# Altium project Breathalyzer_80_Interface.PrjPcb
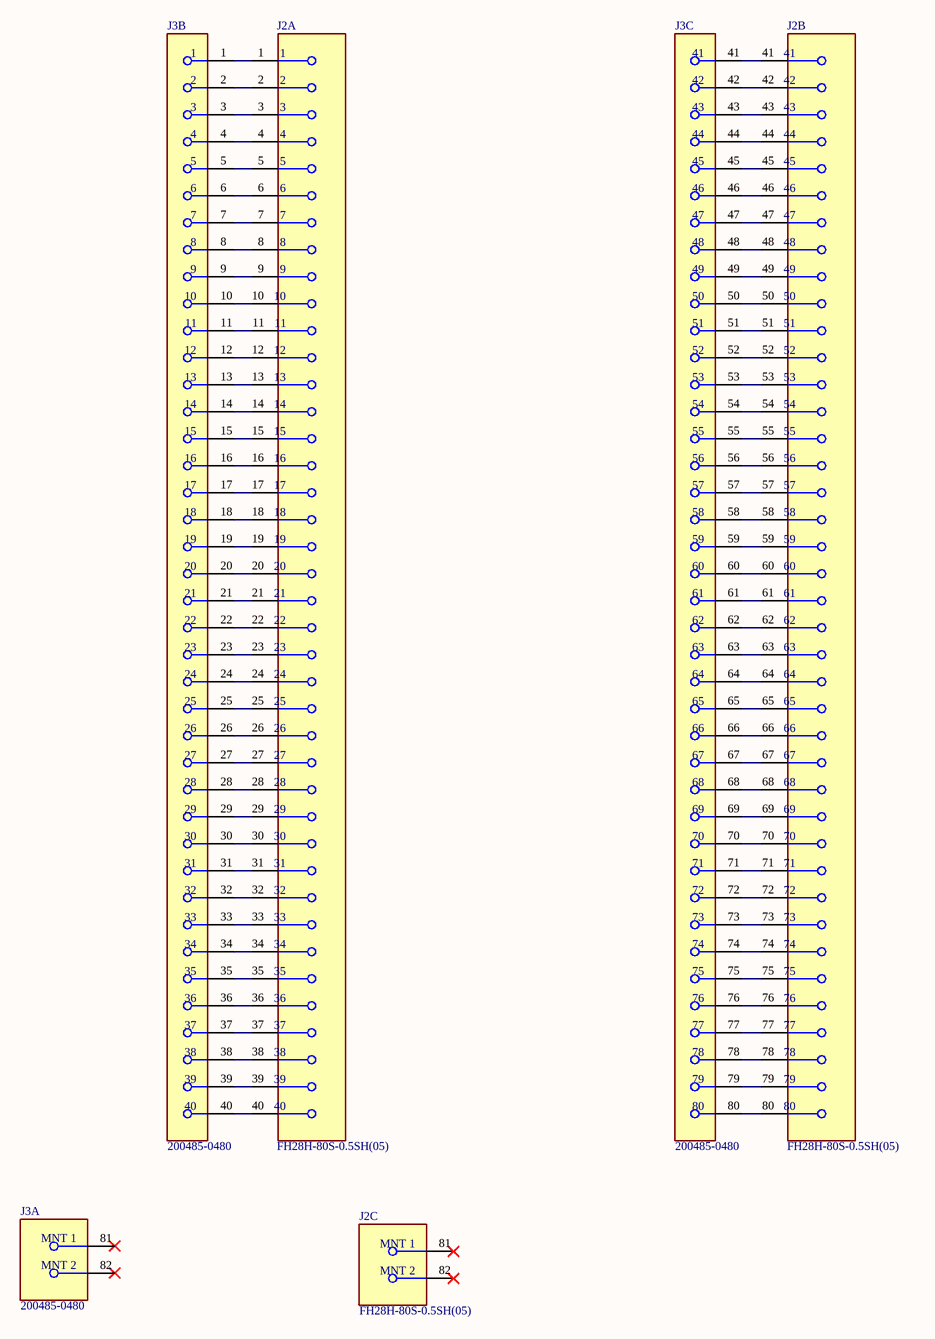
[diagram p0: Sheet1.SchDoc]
CAGE_CODE: ?????; CONTRACT_NUMBER: <CONTRACT NO>; DOC_NO_ASSY_DWG: <ASSY DWG NO>; DOC_NO_BOM: <BOM DOC NO>; DOC_NO_FAB_DWG: <FAB DWG NO>; DOC_NO_SCH_DWG: <SCH DWG NO>; PCB_2_DEC_TOL: +/-.01; PCB_3_DEC_TOL: +/-.010; PCB_ANG_TOL: +/-1/2; PCB_ASSEMBLY_NO: <PCB ASSY NO>; PCB_CHECKER: - -----; PCB_CHECKER_APP_DATE: --/--/----; PCB_DESIGNER: - -----; PCB_DESIGNER_APP_DATE: --/--/----; PCB_DWG_NO: <PCB DWG NO>; PCB_ENGINEER: - -----; PCB_ENGINEER_APP_DATE: --/--/----; PCB_PART_NUMBER: <PCB PN>; PCB_REV: A; SCH_REV: A
1 sheet, 2 parts. Net scope: global (net labels, ports and power ports of the same name join across sheets).
Board file: PCB1.PcbDoc

## Sheet Sheet1.SchDoc
size 431 x 279 mm; SheetNumber: 1; SheetTotal: 1; ENG_APP_DATE: --/--/--; DSN_APP_DATE: --/--/--; CHK_APP_DATE: --/--/--

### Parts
J2  FH28H-80S-0.5SH(05)  [FP-FH28H-80S-0_5SH_05-MFG]  (parts A,B,C of 3)
J3  200485-0480  [FP-200485-0480-MFG]  (parts A,B,C of 3)

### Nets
NetJ2_1: J2.1 J3.1
NetJ2_2: J2.2 J3.2
NetJ2_3: J2.3 J3.3
NetJ2_4: J2.4 J3.4
NetJ2_5: J2.5 J3.5
NetJ2_6: J2.6 J3.6
NetJ2_7: J2.7 J3.7
NetJ2_8: J2.8 J3.8
NetJ2_9: J2.9 J3.9
NetJ2_10: J2.10 J3.10
NetJ2_11: J2.11 J3.11
NetJ2_12: J2.12 J3.12
NetJ2_13: J2.13 J3.13
NetJ2_14: J2.14 J3.14
NetJ2_15: J2.15 J3.15
NetJ2_16: J2.16 J3.16
NetJ2_17: J2.17 J3.17
NetJ2_18: J2.18 J3.18
NetJ2_19: J2.19 J3.19
NetJ2_20: J2.20 J3.20
NetJ2_21: J2.21 J3.21
NetJ2_22: J2.22 J3.22
NetJ2_23: J2.23 J3.23
NetJ2_24: J2.24 J3.24
NetJ2_25: J2.25 J3.25
NetJ2_26: J2.26 J3.26
NetJ2_27: J2.27 J3.27
NetJ2_28: J2.28 J3.28
NetJ2_29: J2.29 J3.29
NetJ2_30: J2.30 J3.30
NetJ2_31: J2.31 J3.31
NetJ2_32: J2.32 J3.32
NetJ2_33: J2.33 J3.33
NetJ2_34: J2.34 J3.34
NetJ2_35: J2.35 J3.35
NetJ2_36: J2.36 J3.36
NetJ2_37: J2.37 J3.37
NetJ2_38: J2.38 J3.38
NetJ2_39: J2.39 J3.39
NetJ2_40: J2.40 J3.40
NetJ2_41: J2.41 J3.41
NetJ2_42: J2.42 J3.42
NetJ2_43: J2.43 J3.43
NetJ2_44: J2.44 J3.44
NetJ2_45: J2.45 J3.45
NetJ2_46: J2.46 J3.46
NetJ2_47: J2.47 J3.47
NetJ2_48: J2.48 J3.48
NetJ2_49: J2.49 J3.49
NetJ2_50: J2.50 J3.50
NetJ2_51: J2.51 J3.51
NetJ2_52: J2.52 J3.52
NetJ2_53: J2.53 J3.53
NetJ2_54: J2.54 J3.54
NetJ2_55: J2.55 J3.55
NetJ2_56: J2.56 J3.56
NetJ2_57: J2.57 J3.57
NetJ2_58: J2.58 J3.58
NetJ2_59: J2.59 J3.59
NetJ2_60: J2.60 J3.60
NetJ2_61: J2.61 J3.61
NetJ2_62: J2.62 J3.62
NetJ2_63: J2.63 J3.63
NetJ2_64: J2.64 J3.64
NetJ2_65: J2.65 J3.65
NetJ2_66: J2.66 J3.66
NetJ2_67: J2.67 J3.67
NetJ2_68: J2.68 J3.68
NetJ2_69: J2.69 J3.69
NetJ2_70: J2.70 J3.70
NetJ2_71: J2.71 J3.71
NetJ2_72: J2.72 J3.72
NetJ2_73: J2.73 J3.73
NetJ2_74: J2.74 J3.74
NetJ2_75: J2.75 J3.75
NetJ2_76: J2.76 J3.76
NetJ2_77: J2.77 J3.77
NetJ2_78: J2.78 J3.78
NetJ2_79: J2.79 J3.79
NetJ2_80: J2.80 J3.80

Not connected (* = marked no-connect by the designer): J2 81(MNT_1)* 82(MNT_2)*; J3 81(MNT_1)* 82(MNT_2)*

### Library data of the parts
J2 = CMP-11609-000031-1: CONN FFC BOTTOM 80POS 0.50MM R/A; Number of Positions: 80; Voltage Rating: 50V; Contact Resistance: 50mR; Max Current Rating: 500mA; Gender: Receptacle; Pitch: 0.5mm; Mating Cycles: 20; Actuator Material: Polymer; Insulation Resistance: 500MR
J3 = CMP-04775-000024-1: 0.5 ONE-TOUCH RA 80P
